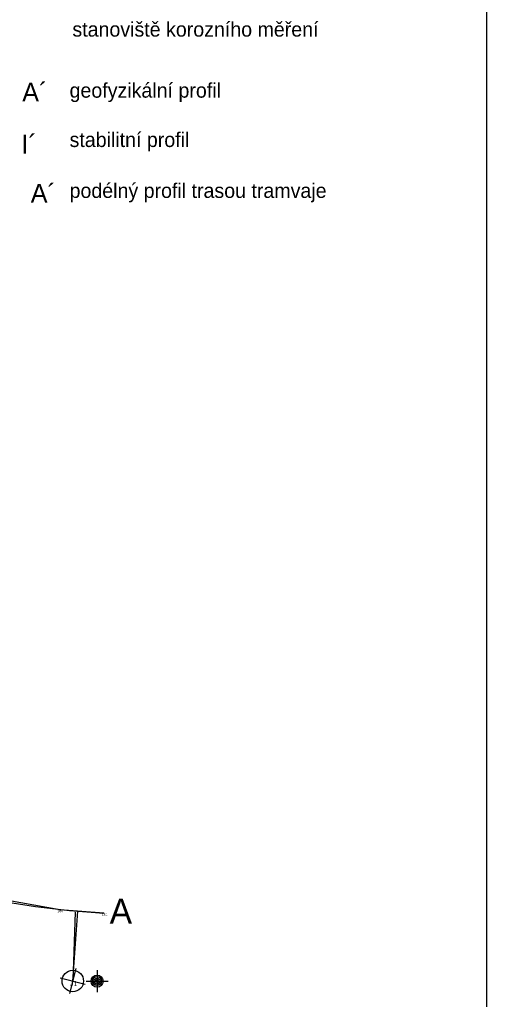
# Model space of a CAD drawing. Extents: x -606444 to -604546, y -1158114 to -1156869.
# Drawn here: x -604748.6 to -604562.3, y -1157651.6 to -1157260.1 of the extents above; entities that cross this region are included whole.
import ezdxf

# ---------------------------------------------------------------- set-up
doc = ezdxf.new("R2010")
doc.units = 0
for name, color, linetype in [('0_sondy', 7, 'Continuous'), ('jádrové vrty_předběžný GTP', 7, 'Continuous'), ('legenda', 7, 'Continuous'), ('netisk', 7, 'Continuous'), ('netisk2', 7, 'Continuous'), ('OSA', 7, 'Continuous'), ('podélný profil trasou tramvaje', 7, 'Continuous'), ('ramecek_tisk', 7, 'Continuous'), ('sondy současného průzkumu', 7, 'Continuous')]:
    doc.layers.add(name, color=color, linetype=linetype)

# ---------------------------------------------------------------- blocks, each defined once
blk = doc.blocks.new('709')
for p, q in [((0, 2.2), (0, -2.2)), ((-2.2, 0), (2.2, 0))]:
    blk.add_line(p, q)
for radius in [1.2, 0.9, 0.6, 0.3]:
    blk.add_circle((0, 0), radius)
blk = doc.blocks.new('IG vrt podr')
at = {"layer": 'sondy současného průzkumu'}
for p, q in [((0.41, 1.65), (-0.42, -1.67)), ((-1.7, 0.42), (1.64, -0.41))]:
    blk.add_line(p, q, dxfattribs=at)
blk.add_circle((0, 0), 1.43, dxfattribs=at)

msp = doc.modelspace()

# ---------------------------------------------------------------- linework, layer by layer
for p, q in [((-604732.59, -1157615.76), (-604732.69, -1157615.66)), ((-604732.59, -1157615.76), (-604732.69, -1157615.86)), ((-604732.59, -1157615.76), (-604732.49, -1157615.66)), ((-604732.59, -1157615.76), (-604732.49, -1157615.86)), ((-604715.01, -1157617.16), (-604715.11, -1157617.06)), ((-604715.01, -1157617.16), (-604715.11, -1157617.26)), ((-604715.01, -1157617.16), (-604714.91, -1157617.06)), ((-604715.01, -1157617.16), (-604714.91, -1157617.26)), ((-604727.4, -1157644.27), (-604727.5, -1157644.17)), ((-604727.4, -1157644.27), (-604727.5, -1157644.37)), ((-604727.4, -1157644.27), (-604727.3, -1157644.17)), ((-604727.4, -1157644.27), (-604727.3, -1157644.37))]:
    msp.add_line(p, q)
at = {"layer": 'netisk'}
msp.add_line((-604726.43, -1157616.73), (-604727.4, -1157644.27), dxfattribs=at)
at = {"layer": 'netisk2'}
msp.add_line((-604727.4, -1157644.27), (-604725.45, -1157616.31), dxfattribs=at)
at = {"layer": 'OSA'}
msp.add_lwpolyline([(-604715.01, -1157617.16), (-604732.59, -1157615.76), (-604777.97, -1157607.65)], dxfattribs=at)
at = {"layer": 'podélný profil trasou tramvaje'}
msp.add_arc((-604692.61, -1157254.61), 363.25, 232.0059, 266.4651, dxfattribs=at)
at = {"layer": 'ramecek_tisk'}
msp.add_line((-604562.25, -1156914.34), (-604562.25, -1158114.34), dxfattribs=at)

# ---------------------------------------------------------------- block references
at = {"layer": '0_sondy', "xscale": 2, "yscale": 2}
msp.add_blockref('709', (-604717.73, -1157644.31), dxfattribs=at)
at = {"layer": 'jádrové vrty_předběžný GTP', "xscale": 3, "yscale": 3}
msp.add_blockref('IG vrt podr', (-604727.4, -1157644.27), dxfattribs=at)

# ---------------------------------------------------------------- texts
for s, height, p in [('160', 1, (-604733.56, -1157616.76)), ('161', 1, (-604715.82, -1157618.16)), ('J1', 2, (-604728.56, -1157646.27))]:
    msp.add_text(s, height=height).set_placement(p)
at = {"layer": 'legenda'}
for s, height, p in [('stanoviště korozního měření', 5.85, (-604727.56, -1157266.92)), ('A´', 7.5, (-604747.59, -1157292.83)), ('geofyzikální profil', 5.85, (-604728.69, -1157291.32)), ('I´', 7.5, (-604747.89, -1157313.62)), ('stabilitní profil', 5.85, (-604728.69, -1157311.03)), ('podélný profil trasou tramvaje', 5.85, (-604728.69, -1157331.37))]:
    msp.add_text(s, height=height, dxfattribs=at).set_placement(p)
at = {"layer": 'podélný profil trasou tramvaje'}
for s, height, p in [('A´', 7.5, (-604744.19, -1157333.25)), ('A', 10, (-604712.67, -1157621.34))]:
    msp.add_text(s, height=height, dxfattribs=at).set_placement(p)

doc.saveas('drawing.dxf')
